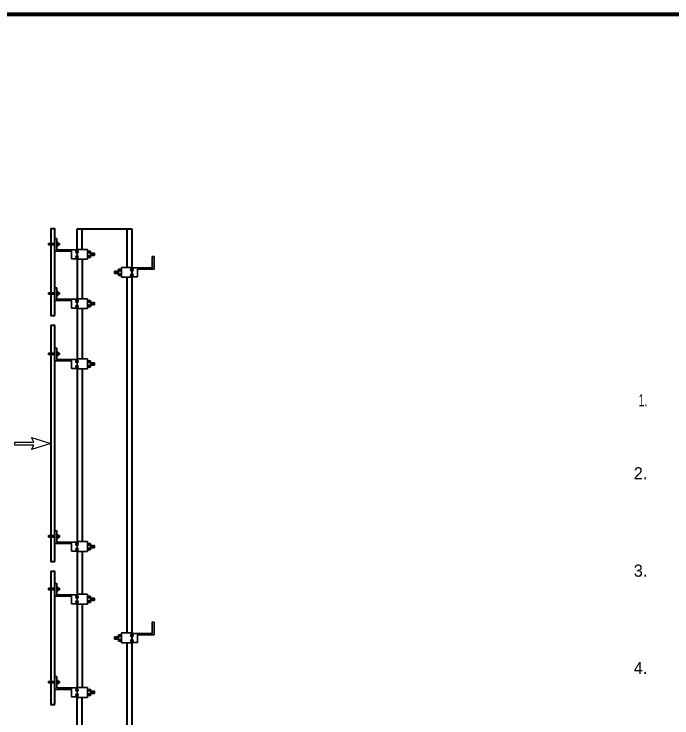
# Model space of a CAD drawing. Extents: x 851 to 1706, y -23 to 521.
# Drawn here: x 1358.6 to 1488.4, y 375.4 to 514.3 of the extents above; entities that cross this region are included whole.
import ezdxf
from ezdxf.enums import TextEntityAlignment as Align

# ---------------------------------------------------------------- set-up
doc = ezdxf.new("R2010")
doc.units = 0
doc.header["$PDMODE"] = 32
doc.header["$PDSIZE"] = 0.5
doc.layers.add('1', color=7, linetype='Continuous', lineweight=35)

msp = doc.modelspace()

# ---------------------------------------------------------------- linework, layer by layer
at = {"layer": '1', "lineweight": 40}
for p, q in [((1371.049, 471.865), (1381.875, 471.865)), ((1371.049, 467.846), (1371.049, 471.865)), ((1371.049, 471.865), (1381.875, 471.865)), ((1372.082, 467.846), (1372.082, 471.865)), ((1380.841, 471.865), (1380.841, 464.292)), ((1381.875, 471.865), (1381.875, 369.717)), ((1371.049, 465.878), (1371.049, 458.114)), ((1372.082, 465.878), (1372.082, 458.114)), ((1380.841, 462.324), (1380.841, 392.176)), ((1371.049, 456.146), (1371.049, 446.222)), ((1372.082, 456.146), (1372.082, 446.222)), ((1371.049, 444.254), (1371.049, 410.192)), ((1372.082, 444.254), (1372.082, 410.192)), ((1371.049, 408.223), (1371.049, 399.803)), ((1372.082, 408.223), (1372.082, 399.803)), ((1371.049, 397.835), (1371.049, 381.433)), ((1372.082, 397.835), (1372.082, 381.433)), ((1380.841, 390.208), (1380.841, 369.717)), ((1371.049, 369.717), (1371.049, 379.464)), ((1372.082, 369.717), (1372.082, 379.464))]:
    msp.add_line(p, q, dxfattribs=at)
at = {"layer": '1'}
for p, q in [((1366.686, 469.979), (1366.686, 467.464)), ((1365.425, 469.022), (1365.425, 468.721)), ((1366.686, 469.022), (1365.425, 469.022)), ((1366.686, 468.721), (1365.425, 468.721)), ((1367.342, 469.186), (1367.047, 469.186)), ((1367.604, 469.022), (1367.047, 469.022)), ((1367.604, 468.721), (1367.047, 468.721)), ((1367.342, 468.557), (1367.047, 468.557)), ((1367.342, 469.186), (1367.342, 468.557)), ((1367.604, 469.022), (1367.604, 468.721)), ((1371.049, 467.846), (1373.116, 467.846)), ((1371.049, 467.163), (1371.049, 467.846)), ((1371.049, 467.163), (1371.049, 466.562)), ((1371.049, 466.124), (1371.049, 466.562)), ((1373.116, 467.846), (1373.116, 465.878)), ((1373.116, 467.464), (1373.726, 467.464)), ((1373.116, 467.163), (1373.726, 467.163)), ((1373.116, 466.562), (1373.726, 466.562)), ((1373.726, 467.464), (1373.726, 466.233)), ((1373.726, 467.108), (1374.461, 467.108)), ((1373.726, 466.616), (1374.461, 466.616)), ((1373.918, 466.972), (1373.918, 466.726)), ((1374.097, 467.108), (1374.097, 466.616)), ((1374.297, 466.972), (1374.297, 466.726)), ((1374.461, 467.108), (1374.461, 466.616)), ((1371.049, 466.124), (1371.049, 465.878)), ((1371.049, 465.878), (1373.116, 465.878)), ((1373.116, 466.233), (1373.726, 466.233)), ((1386.238, 466.425), (1386.238, 463.91)), ((1379.808, 463.91), (1379.197, 463.91)), ((1379.197, 463.91), (1379.197, 462.68)), ((1381.875, 464.293), (1379.808, 464.293)), ((1379.808, 464.293), (1379.808, 462.324)), ((1381.875, 463.609), (1381.875, 464.293)), ((1379.197, 463.554), (1378.463, 463.554)), ((1378.463, 463.554), (1378.463, 463.062)), ((1379.197, 463.062), (1378.463, 463.062)), ((1378.627, 463.418), (1378.627, 463.172)), ((1378.827, 463.554), (1378.827, 463.062)), ((1379.005, 463.418), (1379.005, 463.172)), ((1379.808, 463.609), (1379.197, 463.609)), ((1379.808, 463.008), (1379.197, 463.008)), ((1379.808, 462.68), (1379.197, 462.68)), ((1381.875, 463.609), (1381.875, 463.008)), ((1381.875, 462.57), (1381.875, 463.008)), ((1381.875, 462.57), (1381.875, 462.324)), ((1381.875, 462.324), (1379.808, 462.324)), ((1366.686, 460.247), (1366.686, 457.732)), ((1365.425, 459.29), (1365.425, 458.989)), ((1366.686, 459.29), (1365.425, 459.29)), ((1366.686, 458.989), (1365.425, 458.989)), ((1367.342, 459.454), (1367.047, 459.454)), ((1367.604, 459.29), (1367.047, 459.29)), ((1367.604, 458.989), (1367.047, 458.989)), ((1367.342, 458.825), (1367.047, 458.825)), ((1367.342, 459.454), (1367.342, 458.825)), ((1367.604, 459.29), (1367.604, 458.989)), ((1371.049, 458.114), (1373.116, 458.114)), ((1371.049, 457.431), (1371.049, 458.114)), ((1371.049, 457.431), (1371.049, 456.829)), ((1371.049, 456.392), (1371.049, 456.829)), ((1373.116, 458.114), (1373.116, 456.146)), ((1373.116, 457.732), (1373.726, 457.732)), ((1373.116, 457.431), (1373.726, 457.431)), ((1373.116, 456.829), (1373.726, 456.829)), ((1373.726, 457.732), (1373.726, 456.501)), ((1373.726, 457.376), (1374.461, 457.376)), ((1373.726, 456.884), (1374.461, 456.884)), ((1373.918, 457.239), (1373.918, 456.993)), ((1374.097, 457.376), (1374.097, 456.884)), ((1374.297, 457.239), (1374.297, 456.993)), ((1374.461, 457.376), (1374.461, 456.884)), ((1371.049, 456.392), (1371.049, 456.146)), ((1371.049, 456.146), (1373.116, 456.146)), ((1373.116, 456.501), (1373.726, 456.501)), ((1365.425, 447.398), (1365.425, 447.097)), ((1366.686, 447.398), (1365.425, 447.398)), ((1366.686, 447.097), (1365.425, 447.097)), ((1366.686, 448.355), (1366.686, 445.84)), ((1367.342, 447.562), (1367.047, 447.562)), ((1367.604, 447.398), (1367.047, 447.398)), ((1367.604, 447.097), (1367.047, 447.097)), ((1367.342, 447.562), (1367.342, 446.933)), ((1367.604, 447.398), (1367.604, 447.097)), ((1367.342, 446.933), (1367.047, 446.933)), ((1371.049, 446.222), (1373.116, 446.222)), ((1371.049, 445.539), (1371.049, 446.222)), ((1373.116, 446.222), (1373.116, 444.254)), ((1373.116, 445.84), (1373.726, 445.84)), ((1373.726, 445.84), (1373.726, 444.61)), ((1371.049, 445.539), (1371.049, 444.938)), ((1371.049, 444.5), (1371.049, 444.938)), ((1371.049, 444.5), (1371.049, 444.254)), ((1373.116, 445.539), (1373.726, 445.539)), ((1373.116, 444.938), (1373.726, 444.938)), ((1373.116, 444.61), (1373.726, 444.61)), ((1373.726, 445.484), (1374.461, 445.484)), ((1373.726, 444.992), (1374.461, 444.992)), ((1373.918, 445.348), (1373.918, 445.102)), ((1374.097, 445.484), (1374.097, 444.992)), ((1374.297, 445.348), (1374.297, 445.102)), ((1374.461, 445.484), (1374.461, 444.992)), ((1371.049, 444.254), (1373.116, 444.254)), ((1365.425, 411.367), (1365.425, 411.066)), ((1366.686, 411.367), (1365.425, 411.367)), ((1366.686, 411.066), (1365.425, 411.066)), ((1366.686, 412.324), (1366.686, 409.809)), ((1367.342, 411.531), (1367.047, 411.531)), ((1367.604, 411.367), (1367.047, 411.367)), ((1367.604, 411.066), (1367.047, 411.066)), ((1367.342, 411.531), (1367.342, 410.902)), ((1367.604, 411.367), (1367.604, 411.066)), ((1367.342, 410.902), (1367.047, 410.902)), ((1371.049, 410.192), (1373.116, 410.192)), ((1371.049, 409.508), (1371.049, 410.192)), ((1373.116, 410.192), (1373.116, 408.223)), ((1373.116, 409.809), (1373.726, 409.809)), ((1373.726, 409.809), (1373.726, 408.579)), ((1371.049, 409.508), (1371.049, 408.907)), ((1371.049, 408.469), (1371.049, 408.907)), ((1371.049, 408.469), (1371.049, 408.223)), ((1371.049, 408.223), (1373.116, 408.223)), ((1373.116, 409.508), (1373.726, 409.508)), ((1373.116, 408.907), (1373.726, 408.907)), ((1373.116, 408.579), (1373.726, 408.579)), ((1373.726, 409.454), (1374.461, 409.454)), ((1373.726, 408.961), (1374.461, 408.961)), ((1373.918, 409.317), (1373.918, 409.071)), ((1374.097, 409.454), (1374.097, 408.961)), ((1374.297, 409.317), (1374.297, 409.071)), ((1374.461, 409.454), (1374.461, 408.961)), ((1366.686, 401.936), (1366.686, 399.421)), ((1365.425, 400.979), (1365.425, 400.678)), ((1366.686, 400.979), (1365.425, 400.979)), ((1366.686, 400.678), (1365.425, 400.678)), ((1367.342, 401.143), (1367.047, 401.143)), ((1367.604, 400.979), (1367.047, 400.979)), ((1367.604, 400.678), (1367.047, 400.678)), ((1367.342, 400.514), (1367.047, 400.514)), ((1367.342, 401.143), (1367.342, 400.514)), ((1367.604, 400.979), (1367.604, 400.678)), ((1371.049, 399.803), (1373.116, 399.803)), ((1371.049, 399.12), (1371.049, 399.803)), ((1371.049, 399.12), (1371.049, 398.519)), ((1371.049, 398.081), (1371.049, 398.519)), ((1373.116, 399.803), (1373.116, 397.835)), ((1373.116, 399.421), (1373.726, 399.421)), ((1373.116, 399.12), (1373.726, 399.12)), ((1373.116, 398.519), (1373.726, 398.519)), ((1373.726, 399.421), (1373.726, 398.19)), ((1373.726, 399.065), (1374.461, 399.065)), ((1373.726, 398.573), (1374.461, 398.573)), ((1373.918, 398.929), (1373.918, 398.683)), ((1374.097, 399.065), (1374.097, 398.573)), ((1374.297, 398.929), (1374.297, 398.683)), ((1374.461, 399.065), (1374.461, 398.573)), ((1371.049, 398.081), (1371.049, 397.835)), ((1371.049, 397.835), (1373.116, 397.835)), ((1373.116, 398.19), (1373.726, 398.19)), ((1386.238, 394.308), (1386.238, 391.793)), ((1379.808, 391.793), (1379.197, 391.793)), ((1379.197, 391.793), (1379.197, 390.563)), ((1381.875, 392.176), (1379.808, 392.176)), ((1379.808, 392.176), (1379.808, 390.208)), ((1381.875, 391.493), (1381.875, 392.176)), ((1379.197, 391.438), (1378.463, 391.438)), ((1378.463, 391.438), (1378.463, 390.946)), ((1379.197, 390.946), (1378.463, 390.946)), ((1378.627, 391.301), (1378.627, 391.055)), ((1378.827, 391.438), (1378.827, 390.946)), ((1379.005, 391.301), (1379.005, 391.055)), ((1379.808, 391.493), (1379.197, 391.493)), ((1379.808, 390.891), (1379.197, 390.891)), ((1379.808, 390.563), (1379.197, 390.563)), ((1381.875, 390.208), (1379.808, 390.208)), ((1381.875, 391.493), (1381.875, 390.891)), ((1381.875, 390.454), (1381.875, 390.891)), ((1381.875, 390.454), (1381.875, 390.208)), ((1366.686, 383.565), (1366.686, 381.05)), ((1365.425, 382.608), (1365.425, 382.307)), ((1366.686, 382.608), (1365.425, 382.608)), ((1366.686, 382.307), (1365.425, 382.307)), ((1367.342, 382.772), (1367.047, 382.772)), ((1367.604, 382.608), (1367.047, 382.608)), ((1367.604, 382.307), (1367.047, 382.307)), ((1367.342, 382.143), (1367.047, 382.143)), ((1367.342, 382.772), (1367.342, 382.143)), ((1367.604, 382.608), (1367.604, 382.307)), ((1371.049, 381.433), (1373.116, 381.433)), ((1371.049, 380.749), (1371.049, 381.433)), ((1371.049, 380.749), (1371.049, 380.148)), ((1373.116, 381.433), (1373.116, 379.464)), ((1373.116, 380.749), (1373.726, 380.749)), ((1373.726, 380.694), (1374.461, 380.694)), ((1373.918, 380.558), (1373.918, 380.312)), ((1374.097, 380.694), (1374.097, 380.202)), ((1374.297, 380.558), (1374.297, 380.312)), ((1374.461, 380.694), (1374.461, 380.202)), ((1371.049, 379.71), (1371.049, 380.148)), ((1371.049, 379.71), (1371.049, 379.464)), ((1371.049, 379.464), (1373.116, 379.464)), ((1373.116, 380.148), (1373.726, 380.148)), ((1373.726, 380.202), (1374.461, 380.202))]:
    msp.add_line(p, q, dxfattribs=at)
at = {"layer": '1', "lineweight": 25}
for q in [(1385.844, 394.308), (1386.238, 391.793)]:
    msp.add_line((1386.238, 394.308), q, dxfattribs=at)
at = {"layer": '1', "lineweight": 158}
msp.add_lwpolyline([(1699.744, 514.252), (908.044, 514.152), (908.144, -11.848)], dxfattribs=at)
at = {"layer": '1', "lineweight": 40}
for points in [[(1366.686, 454.806), (1366.686, 471.865), (1365.856, 471.865), (1365.856, 454.806)], [(1366.686, 406.255), (1366.686, 452.838), (1365.856, 452.838), (1365.856, 406.255)], [(1366.686, 378.043), (1366.686, 404.287), (1365.856, 404.287), (1365.856, 378.043)]]:
    msp.add_lwpolyline(points, close=True, dxfattribs=at)
at = {"layer": '1', "lineweight": 25}
for points in [[(1366.686, 469.979), (1367.047, 469.979), (1367.047, 467.764)], [(1366.686, 460.247), (1367.047, 460.247), (1367.047, 458.032)], [(1366.686, 448.355), (1367.047, 448.355), (1367.047, 446.14)], [(1366.686, 412.324), (1367.047, 412.324), (1367.047, 410.11)], [(1366.686, 401.936), (1367.047, 401.936), (1367.047, 399.721)], [(1366.686, 401.936), (1367.047, 401.936), (1367.047, 399.721)], [(1366.686, 383.565), (1367.047, 383.565), (1367.047, 381.351)]]:
    msp.add_lwpolyline(points, dxfattribs=at)
at = {"layer": '1'}
for points in [[(1366.686, 469.979), (1367.047, 469.979), (1367.047, 467.764), (1371.049, 467.764)], [(1371.049, 465.987), (1369.966, 465.987), (1369.966, 467.464), (1366.686, 467.464)], [(1386.238, 466.425), (1385.877, 466.425), (1385.877, 464.211), (1381.875, 464.211)], [(1381.875, 462.434), (1382.957, 462.434), (1382.957, 463.91), (1386.238, 463.91)], [(1366.686, 460.247), (1367.047, 460.247), (1367.047, 458.032), (1371.049, 458.032)], [(1371.049, 456.255), (1369.966, 456.255), (1369.966, 457.732), (1366.686, 457.732)], [(1366.686, 448.355), (1367.047, 448.355), (1367.047, 446.14), (1371.049, 446.14)], [(1371.049, 444.364), (1369.966, 444.364), (1369.966, 445.84), (1366.686, 445.84)], [(1366.686, 412.324), (1367.047, 412.324), (1367.047, 410.11), (1371.049, 410.11)], [(1371.049, 408.333), (1369.966, 408.333), (1369.966, 409.809), (1366.686, 409.809)], [(1366.686, 401.936), (1367.047, 401.936), (1367.047, 399.721), (1371.049, 399.721)], [(1371.049, 397.944), (1369.966, 397.944), (1369.966, 399.421), (1366.686, 399.421)], [(1386.238, 394.308), (1385.877, 394.308), (1385.877, 392.094), (1381.875, 392.094)], [(1381.875, 390.317), (1382.957, 390.317), (1382.957, 391.793), (1386.238, 391.793)], [(1366.686, 383.565), (1367.047, 383.565), (1367.047, 381.351), (1371.049, 381.351)], [(1371.049, 379.574), (1369.966, 379.574), (1369.966, 381.05), (1366.686, 381.05)], [(1373.116, 381.05), (1373.726, 381.05), (1373.726, 379.82), (1373.116, 379.82)]]:
    msp.add_lwpolyline(points, dxfattribs=at)
at = {"layer": '1', "lineweight": 25}
msp.add_lwpolyline([(1362.51, 429.246), (1358.77, 429.246), (1358.77, 429.82), (1362.51, 429.82), (1362.083, 430.722), (1365.856, 429.546), (1362.083, 428.344)], close=True, dxfattribs=at)
msp.add_lwpolyline([(1362.51, 429.246), (1358.77, 429.246), (1358.77, 429.82), (1362.51, 429.82), (1362.083, 430.722), (1365.856, 429.546), (1362.083, 428.344)], close=True, dxfattribs=at)
at = {"layer": '1'}
for p in [(1371.049, 467.354), (1371.049, 466.315), (1381.875, 463.8), (1381.875, 462.762), (1371.049, 457.622), (1371.049, 456.583), (1371.049, 445.73), (1371.049, 444.692), (1371.049, 409.7), (1371.049, 408.661), (1371.049, 399.311), (1371.049, 398.272), (1381.875, 391.684), (1381.875, 390.645), (1371.049, 380.94), (1371.049, 379.902)]:
    msp.add_point(p, dxfattribs=at)

# ---------------------------------------------------------------- texts
at = {"layer": '1', "width": 0.65}
msp.add_text('1.', height=2.4, dxfattribs=at).set_placement((1483.588, 436.869), align=Align.RIGHT)
at = {"layer": '1'}
for s, p in [('2.', (1483.588, 422.469)), ('3.', (1483.588, 403.269)), ('4.', (1483.588, 384.069))]:
    msp.add_text(s, height=2.4, dxfattribs=at).set_placement(p, align=Align.RIGHT)

doc.saveas('drawing.dxf')
